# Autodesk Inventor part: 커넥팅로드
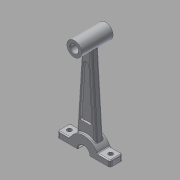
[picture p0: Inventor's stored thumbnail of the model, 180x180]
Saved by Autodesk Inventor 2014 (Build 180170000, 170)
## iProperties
Created: 2016-11
Part Number: 커넥팅로드
Material: 알루미늄 6061
Document SubType Name: Modeling
Designer: mduedu
Density: 2.71 g/cm^3
Mass: 44.549 g
Surface Area: 86.7069 cm^2
Volume: 16.4387 cm^3
Appearance: 알루미늄 - 평지
Author: mduedu
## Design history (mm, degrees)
sketch "스케치1" dims "d0" = 30, "d3" = 15
  geometry: L1 (0, 0)-(0, 96); L2 (-5, 90.41)-(-10, 11.18); L3 (5, 90.41)-(10, 11.18); C1 r 6 at (0, 0); C2 r 4 at (0, 96); 3 further points
  constraints: 6 end point, 4 coincident, 2 centre point, 2 symmetric about line, 1 vertical, 6 other
  dimensions: "d1" = 12 diameter of C1; "d2" = 8 diameter of C2; "d4" = 96 distance of L1.start L1.end; "d6" = 10 distance from line of L1 L2.end; "d7" = 5 distance from line of L1 L2.start
extrude "돌출1" new body sketch "스케치1" stored distance "d8" = 13; taper "d9" = 0 deg
extrude "돌출2" join sketch "스케치1" stored distance "d10" = 32; taper "d11" = 0 deg
sketch "스케치2"
  geometry: L1 (5, 90.41)-(10, 11.18) reference; L2 (-5, 90.41)-(-10, 11.18) reference; A1 r 7.5 centre (0, 96) between (5, 90.41) and (-5, 90.41) reference; A2 r 15 centre (0, 0) between (10, 11.18) and (-10, 11.18) reference
extrude "돌출3" join sketch "스케치2" stored distance "d12" = 8; taper "d13" = 0 deg
sketch "스케치3"
  geometry: L1 (-2.732, 78.715)-(-6.171, 24.226); L2 (2.732, 78.715)-(6.171, 24.226); L3 (0, 78.5)-(0, 25); A1 r 17.5 centre (0, 96) between (-2.732, 78.715) and (2.732, 78.715); A2 r 25 centre (0, 0) between (6.171, 24.226) and (-6.171, 24.226); 9 further points; 2 other entities
  constraints: 6 end point, 6 point on circle, 2 centre point, 1 symmetric about line, 1 vertical alignment, 6 other
  dimensions: "d18" = 10 dimension on A1; "d19" = 10 dimension on A2; "d20" = 3 dimension on L1
extrude "돌출4" cut sketch "스케치3" distance "d21" = 2; taper "d22" = 0 deg
fillet "모깎기1" dims "d23" = 2
fillet "모깎기2" dims "d24" = 2
fillet "모깎기3" dims "d25" = 1
chamfer "모따기1" distance "d26" = 0.5; stored, may be unused: second distance "d27" = 2, angle "d28" = 45 deg
sketch "스케치4"
  geometry: L1 (-27, -6)-(-13.748, -6); L2 (27, -6)-(27, 6); L3 (27, 6)-(13.748, 6); L4 (-27, 6)-(-27, -6); L5 (-27, -6)-(27, 6); L6 (27, -6)-(-27, 6); L7 (-13.748, 6)-(-27, 6); L8 (13.748, 6)-(-13.748, 6); L9 (13.748, -6)-(27, -6); L10 (-13.748, -6)-(13.748, -6); A1 r 15 centre (0, 0) between (-13.748, 6) and (13.748, 6) reference; 1 further point
  constraints: 20 end point, 10 parallel, 4 point on circle, 3 horizontal, 3 perpendicular, 2 midpoint
  dimensions: "d29" = 54 distance of L1.start L2.start; "d31" = 12 distance of L2.start L2.end
extrude "돌출5" join sketch "스케치4" stored distance "d32" = 0; taper "d33" = 0 deg
fillet "모깎기4" dims "d34" = 2
fillet "모깎기5" dims "d35" = 1
fillet "모깎기6" dims "d36" = 1
sketch "스케치5"
  geometry: L1 (1, 0)-(1, 9) reference; L2 (-18.5, 20.5)-(-33.5, 20.5) reference; L3 (-33.5, -11.5)-(-18.5, -11.5) reference; L4 (-26, 20.5)-(-26, -11.5); 3 further points
  constraints: 2 end point, 2 midpoint, 1 horizontal alignment, 1 symmetric about line
  dimensions: "d37" = 6 distance from line of point (-5, 4.5) L1
feature "분할1"
sketch "스케치7"
  geometry: 2 further points
  constraints: 2 other
hole "구멍2" sketch "스케치7" at (-47, 4.5), (-5, 4.5) diameter "d45" = 4.5; stored, may be unused: countersink angle "d49" = 90 deg, drill point angle "d51" = 0 deg; dims "d46" = 6, "d47" = 4, "d48" = 2, "d50" = 8
node "솔리드1"
mirror "대칭1"
other parameters: "d16" = 4, "d17" = 4
